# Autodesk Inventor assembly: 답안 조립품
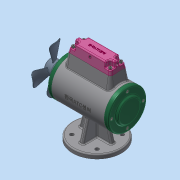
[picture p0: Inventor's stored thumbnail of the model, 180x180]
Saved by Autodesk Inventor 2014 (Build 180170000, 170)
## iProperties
Created: 2023-01
Part Number: 답안 조립품
Document SubType Name: Assembly
Designer: dg
Author: dg
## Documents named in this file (19)
- C:\Users\dg\Desktop\630106V1017 (1)\답안 조립품.iam
- C:\Users\dg\Desktop\630106V1017 (1)\본체.ipt
- C:\Users\dg\Desktop\630106V1017 (1)\축.ipt
- C:\Users\dg\Desktop\630106V1017 (1)\키 5 x 5 x 18.ipt
- C:\Users\dg\Desktop\630106V1017 (1)\베어링 6203.ipt
- C:\Users\dg\Desktop\630106V1017 (1)\뒤커버.ipt
- C:\Users\dg\Desktop\630106V1017 (1)\앞커버.ipt
- C:\Users\dg\Desktop\630106V1017 (1)\볼트 M4 x 12.ipt
- C:\Users\dg\Desktop\630106V1017 (1)\오일실 17 30 8.ipt
- C:\Users\dg\Desktop\630106V1017 (1)\멈춤나사 M4 x 8.ipt
- C:\Users\dg\Desktop\630106V1017 (1)\팬날개.ipt
- 팬날개.ipt
- C:\Users\dg\Desktop\630106V1017 (1)\부시.ipt
- C:\Users\dg\Desktop\630106V1017 (1)\헤더커버.ipt
- C:\Users\dg\Desktop\630106V1017 (1)\볼트 M4 x 16.ipt
- C:\Users\dg\Desktop\630106V1017 (1)\가변스프링1.ipt
- C:\Users\dg\Desktop\630106V1017 (1)\슬라이드.ipt
- C:\Users\dg\Desktop\630106V1017 (1)\가변스프링2.ipt
- C:\Users\dg\Desktop\630106V1017 (1)\가변스프링3.ipt
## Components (4 placed, 4 different names)
1. 헤더커버:1
2. 가변스프링1:1
3. 가변스프링2:1
4. 가변스프링3:1
